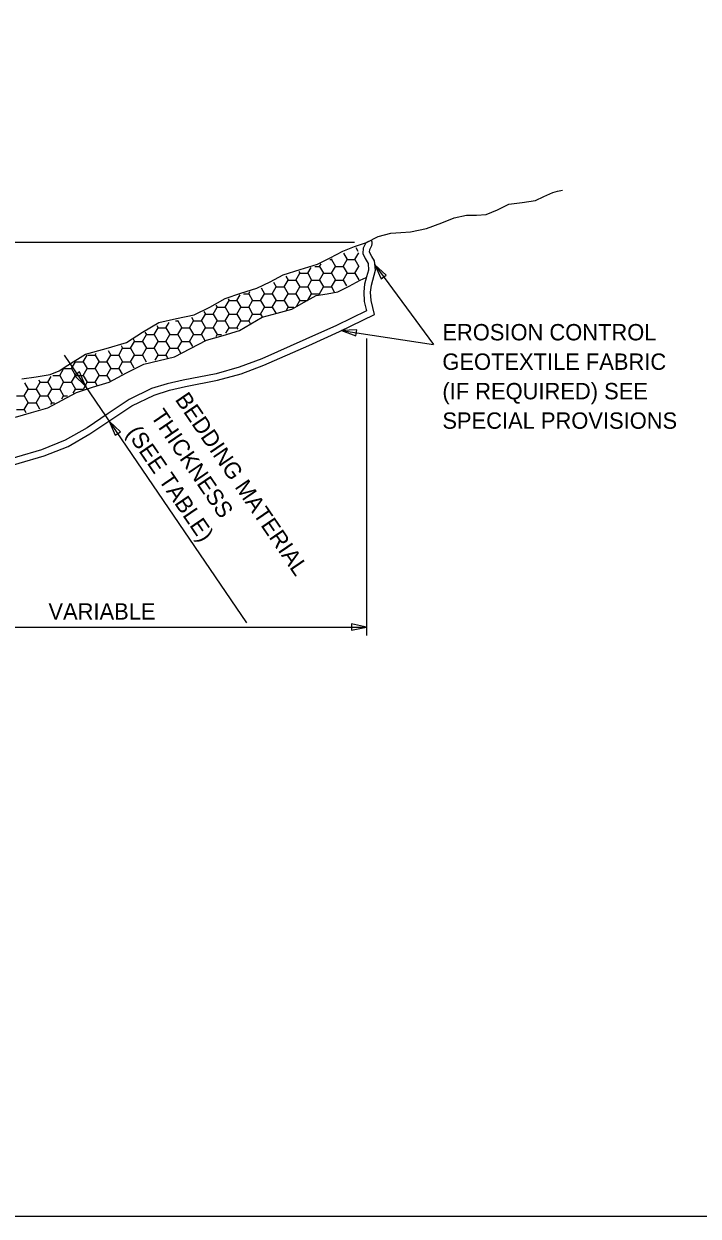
# Model space of a CAD drawing. Extents: x -439.1 to -407.9, y -458.1 to -436.2.
# Drawn here: x -424.66 to -418.48, y -458.05 to -447.12 of the extents above; entities that cross this region are included whole.
import ezdxf

# ---------------------------------------------------------------- set-up
doc = ezdxf.new("R2010")
doc.units = 0
doc.layers.add('Default', color=7, linetype='Continuous')
doc.layers.add('Draft_Named_Boundary', color=7, linetype='Continuous')

msp = doc.modelspace()

# ---------------------------------------------------------------- linework, layer by layer
at = {"layer": 'Default'}
for p, q in [((-421.625, -449.128), (-427.35, -449.128)), ((-421.613, -449.174), (-421.595, -449.206)), ((-421.523, -449.13), (-421.515, -449.128)), ((-421.472, -449.106), (-421.515, -449.128)), ((-421.851, -449.284), (-421.838, -449.284)), ((-421.838, -449.284), (-421.833, -449.276)), ((-421.838, -449.284), (-421.802, -449.347)), ((-421.73, -449.347), (-421.694, -449.284)), ((-421.727, -449.227), (-421.694, -449.284)), ((-421.694, -449.284), (-421.622, -449.284)), ((-421.622, -449.284), (-421.587, -449.224)), ((-421.622, -449.284), (-421.586, -449.347)), ((-422.163, -449.472), (-422.127, -449.409)), ((-422.135, -449.395), (-422.127, -449.409)), ((-422.127, -449.409), (-422.055, -449.409)), ((-422.055, -449.409), (-422.025, -449.358)), ((-422.055, -449.409), (-422.019, -449.472)), ((-421.991, -449.347), (-421.946, -449.347)), ((-421.946, -449.347), (-421.932, -449.322)), ((-421.946, -449.347), (-421.91, -449.409)), ((-421.946, -449.472), (-421.91, -449.409)), ((-421.91, -449.409), (-421.838, -449.409)), ((-421.838, -449.409), (-421.802, -449.347)), ((-421.838, -449.409), (-421.802, -449.472)), ((-421.802, -449.347), (-421.73, -449.347)), ((-421.73, -449.347), (-421.694, -449.409)), ((-421.73, -449.472), (-421.694, -449.409)), ((-421.694, -449.409), (-421.622, -449.409)), ((-421.622, -449.409), (-421.586, -449.347)), ((-421.622, -449.409), (-421.587, -449.47)), ((-421.44, -449.332), (-420.903, -450.062)), ((-422.369, -449.491), (-422.343, -449.534)), ((-422.271, -449.534), (-422.235, -449.472)), ((-422.255, -449.437), (-422.235, -449.472)), ((-422.235, -449.472), (-422.163, -449.472)), ((-422.163, -449.472), (-422.127, -449.534)), ((-422.055, -449.534), (-422.019, -449.472)), ((-422.019, -449.472), (-421.946, -449.472)), ((-421.946, -449.472), (-421.91, -449.534)), ((-421.838, -449.534), (-421.802, -449.472)), ((-421.802, -449.472), (-421.73, -449.472)), ((-421.73, -449.472), (-421.699, -449.526)), ((-422.704, -449.659), (-422.674, -449.607)), ((-422.643, -449.597), (-422.596, -449.597)), ((-422.596, -449.597), (-422.585, -449.577)), ((-422.596, -449.597), (-422.56, -449.659)), ((-422.488, -449.659), (-422.452, -449.597)), ((-422.483, -449.543), (-422.452, -449.597)), ((-422.452, -449.597), (-422.38, -449.597)), ((-422.38, -449.597), (-422.343, -449.534)), ((-422.38, -449.597), (-422.343, -449.659)), ((-422.343, -449.534), (-422.271, -449.534)), ((-422.271, -449.534), (-422.235, -449.597)), ((-422.271, -449.659), (-422.235, -449.597)), ((-422.235, -449.597), (-422.163, -449.597)), ((-422.163, -449.597), (-422.127, -449.534)), ((-422.163, -449.597), (-422.127, -449.659)), ((-422.127, -449.534), (-422.055, -449.534)), ((-422.055, -449.534), (-422.019, -449.597)), ((-422.053, -449.657), (-422.019, -449.597)), ((-422.019, -449.597), (-421.946, -449.597)), ((-421.946, -449.597), (-421.91, -449.534)), ((-421.946, -449.597), (-421.944, -449.602)), ((-421.91, -449.534), (-421.838, -449.534)), ((-421.838, -449.534), (-421.812, -449.579)), ((-422.921, -449.784), (-422.885, -449.722)), ((-422.896, -449.703), (-422.885, -449.722)), ((-422.885, -449.722), (-422.813, -449.722)), ((-422.813, -449.722), (-422.776, -449.659)), ((-422.813, -449.722), (-422.776, -449.784)), ((-422.785, -449.645), (-422.776, -449.659)), ((-422.776, -449.659), (-422.704, -449.659)), ((-422.704, -449.659), (-422.668, -449.722)), ((-422.704, -449.784), (-422.668, -449.722)), ((-422.668, -449.722), (-422.596, -449.722)), ((-422.596, -449.722), (-422.56, -449.659)), ((-422.596, -449.722), (-422.56, -449.784)), ((-422.56, -449.659), (-422.488, -449.659)), ((-422.488, -449.659), (-422.452, -449.722)), ((-422.488, -449.784), (-422.452, -449.722)), ((-422.452, -449.722), (-422.38, -449.722)), ((-422.38, -449.722), (-422.343, -449.659)), ((-422.38, -449.722), (-422.348, -449.776)), ((-422.343, -449.659), (-422.271, -449.659)), ((-422.271, -449.659), (-422.235, -449.722)), ((-422.25, -449.748), (-422.235, -449.722)), ((-422.235, -449.722), (-422.182, -449.722)), ((-422.155, -449.708), (-422.127, -449.659)), ((-422.127, -449.659), (-422.058, -449.659)), ((-423.268, -449.847), (-423.246, -449.847)), ((-423.246, -449.847), (-423.242, -449.841)), ((-423.246, -449.847), (-423.209, -449.909)), ((-423.137, -449.909), (-423.101, -449.847)), ((-423.121, -449.812), (-423.101, -449.847)), ((-423.101, -449.847), (-423.029, -449.847)), ((-423.029, -449.847), (-422.993, -449.784)), ((-423.029, -449.847), (-422.993, -449.909)), ((-423.007, -449.761), (-422.993, -449.784)), ((-422.993, -449.784), (-422.921, -449.784)), ((-422.921, -449.784), (-422.885, -449.847)), ((-422.921, -449.909), (-422.885, -449.847)), ((-422.885, -449.847), (-422.813, -449.847)), ((-422.813, -449.847), (-422.776, -449.784)), ((-422.813, -449.847), (-422.776, -449.909)), ((-422.776, -449.784), (-422.704, -449.784)), ((-422.704, -449.784), (-422.668, -449.847)), ((-422.704, -449.909), (-422.668, -449.847)), ((-422.668, -449.847), (-422.596, -449.847)), ((-422.596, -449.847), (-422.56, -449.784)), ((-422.596, -449.847), (-422.583, -449.87)), ((-422.56, -449.784), (-422.488, -449.784)), ((-422.488, -449.784), (-422.47, -449.815)), ((-423.547, -449.95), (-423.534, -449.972)), ((-423.462, -449.972), (-423.426, -449.909)), ((-423.438, -449.888), (-423.426, -449.909)), ((-423.426, -449.909), (-423.354, -449.909)), ((-423.354, -449.909), (-423.325, -449.86)), ((-423.354, -449.909), (-423.318, -449.972)), ((-423.246, -449.972), (-423.209, -449.909)), ((-423.209, -449.909), (-423.137, -449.909)), ((-423.137, -449.909), (-423.101, -449.972)), ((-423.029, -449.972), (-422.993, -449.909)), ((-422.993, -449.909), (-422.921, -449.909)), ((-422.921, -449.909), (-422.885, -449.972)), ((-422.805, -449.958), (-422.776, -449.909)), ((-422.776, -449.909), (-422.704, -449.909)), ((-422.704, -449.909), (-422.697, -449.922)), ((-421.747, -449.934), (-420.903, -450.062)), ((-423.765, -450.072), (-423.751, -450.097)), ((-423.679, -450.097), (-423.642, -450.034)), ((-423.656, -450.011), (-423.642, -450.034)), ((-423.642, -450.034), (-423.57, -450.034)), ((-423.57, -450.034), (-423.534, -449.972)), ((-423.57, -450.034), (-423.534, -450.097)), ((-423.534, -449.972), (-423.462, -449.972)), ((-423.462, -449.972), (-423.426, -450.034)), ((-423.462, -450.097), (-423.426, -450.034)), ((-423.426, -450.034), (-423.354, -450.034)), ((-423.354, -450.034), (-423.318, -449.972)), ((-423.354, -450.034), (-423.318, -450.097)), ((-423.318, -449.972), (-423.246, -449.972)), ((-423.246, -449.972), (-423.209, -450.034)), ((-423.246, -450.097), (-423.209, -450.034)), ((-423.209, -450.034), (-423.137, -450.034)), ((-423.137, -450.034), (-423.101, -449.972)), ((-423.137, -450.034), (-423.11, -450.082)), ((-423.101, -449.972), (-423.029, -449.972)), ((-423.029, -449.972), (-422.997, -450.027)), ((-422.894, -449.988), (-422.885, -449.972)), ((-422.885, -449.972), (-422.846, -449.972)), ((-421.515, -450.009), (-421.515, -452.73)), ((-424.286, -450.159), (-422.615, -452.612)), ((-424.112, -450.222), (-424.076, -450.161)), ((-424.07, -450.159), (-424.003, -450.159)), ((-424.003, -450.159), (-423.993, -450.142)), ((-424.003, -450.159), (-423.967, -450.222)), ((-423.895, -450.222), (-423.859, -450.159)), ((-423.883, -450.118), (-423.859, -450.159)), ((-423.859, -450.159), (-423.787, -450.159)), ((-423.787, -450.159), (-423.751, -450.097)), ((-423.787, -450.159), (-423.751, -450.222)), ((-423.751, -450.097), (-423.679, -450.097)), ((-423.679, -450.097), (-423.642, -450.159)), ((-423.679, -450.222), (-423.642, -450.159)), ((-423.642, -450.159), (-423.57, -450.159)), ((-423.57, -450.159), (-423.534, -450.097)), ((-423.57, -450.159), (-423.536, -450.22)), ((-423.534, -450.097), (-423.462, -450.097)), ((-423.462, -450.097), (-423.426, -450.159)), ((-423.452, -450.205), (-423.426, -450.159)), ((-423.426, -450.159), (-423.354, -450.159)), ((-423.354, -450.159), (-423.318, -450.097)), ((-423.354, -450.159), (-423.339, -450.185)), ((-423.318, -450.097), (-423.246, -450.097)), ((-423.246, -450.097), (-423.222, -450.138)), ((-424.328, -450.347), (-424.292, -450.285)), ((-424.292, -450.284), (-424.22, -450.284)), ((-424.22, -450.284), (-424.184, -450.222)), ((-424.22, -450.284), (-424.184, -450.347)), ((-424.186, -450.218), (-424.184, -450.222)), ((-424.184, -450.222), (-424.112, -450.222)), ((-424.112, -450.222), (-424.075, -450.284)), ((-424.112, -450.347), (-424.075, -450.284)), ((-424.075, -450.284), (-424.003, -450.284)), ((-424.003, -450.284), (-423.967, -450.222)), ((-424.003, -450.284), (-423.967, -450.347)), ((-423.967, -450.222), (-423.895, -450.222)), ((-423.895, -450.222), (-423.859, -450.284)), ((-423.895, -450.347), (-423.859, -450.284)), ((-423.859, -450.284), (-423.787, -450.284)), ((-423.787, -450.284), (-423.751, -450.222)), ((-423.787, -450.284), (-423.757, -450.336)), ((-423.751, -450.222), (-423.679, -450.222)), ((-423.679, -450.222), (-423.648, -450.275)), ((-424.521, -450.388), (-424.508, -450.409)), ((-424.436, -450.409), (-424.406, -450.357)), ((-424.391, -450.347), (-424.328, -450.347)), ((-424.328, -450.347), (-424.292, -450.409)), ((-424.22, -450.409), (-424.184, -450.347)), ((-424.184, -450.347), (-424.112, -450.347)), ((-424.112, -450.347), (-424.075, -450.409)), ((-424.003, -450.409), (-423.967, -450.347)), ((-423.967, -450.347), (-423.895, -450.347)), ((-423.895, -450.347), (-423.866, -450.397)), ((-424.653, -450.534), (-424.617, -450.472)), ((-424.651, -450.413), (-424.617, -450.472)), ((-424.617, -450.472), (-424.545, -450.472)), ((-424.545, -450.472), (-424.508, -450.409)), ((-424.545, -450.472), (-424.508, -450.534)), ((-424.508, -450.409), (-424.436, -450.409)), ((-424.436, -450.409), (-424.4, -450.472)), ((-424.436, -450.534), (-424.4, -450.472)), ((-424.4, -450.472), (-424.328, -450.472)), ((-424.328, -450.472), (-424.292, -450.409)), ((-424.328, -450.472), (-424.292, -450.534)), ((-424.292, -450.409), (-424.22, -450.409)), ((-424.22, -450.409), (-424.184, -450.472)), ((-424.205, -450.508), (-424.184, -450.472)), ((-424.184, -450.472), (-424.112, -450.472)), ((-424.111, -450.472), (-424.075, -450.409)), ((-424.085, -450.44), (-424.091, -450.445)), ((-424.075, -450.409), (-424.003, -450.409)), ((-424.003, -450.409), (-423.988, -450.436)), ((-424.725, -450.534), (-424.653, -450.534)), ((-424.653, -450.534), (-424.617, -450.597)), ((-424.653, -450.659), (-424.617, -450.597)), ((-424.617, -450.597), (-424.545, -450.597)), ((-424.545, -450.597), (-424.508, -450.534)), ((-424.545, -450.597), (-424.512, -450.653)), ((-424.508, -450.534), (-424.436, -450.534)), ((-424.436, -450.534), (-424.4, -450.597)), ((-424.41, -450.614), (-424.4, -450.597)), ((-424.4, -450.597), (-424.377, -450.597)), ((-424.307, -450.561), (-424.292, -450.534)), ((-424.292, -450.534), (-424.255, -450.534)), ((-424.725, -450.659), (-424.653, -450.659)), ((-424.653, -450.659), (-424.638, -450.685)), ((-423.868, -450.759), (-423.874, -450.764)), ((-426.203, -452.652), (-421.515, -452.652))]:
    msp.add_line(p, q, dxfattribs=at)
for points in [[(-421.515, -449.128), (-421.408, -449.074), (-421.292, -449.042), (-421.202, -449.035), (-421.112, -449.031), (-420.967, -449.001), (-420.826, -448.948), (-420.714, -448.903), (-420.6, -448.877), (-420.509, -448.877), (-420.421, -448.871), (-420.317, -448.827), (-420.213, -448.778), (-420.09, -448.76), (-419.969, -448.743), (-419.89, -448.707), (-419.81, -448.669), (-419.766, -448.656), (-419.72, -448.647)], [(-424.675, -450.378), (-424.545, -450.36), (-424.416, -450.339), (-424.332, -450.303), (-424.253, -450.252), (-424.093, -450.152), (-423.903, -450.098), (-423.715, -450.043), (-423.568, -449.949), (-423.419, -449.86), (-423.258, -449.824), (-423.095, -449.791), (-422.953, -449.719), (-422.813, -449.641), (-422.667, -449.593), (-422.52, -449.547), (-422.4, -449.487), (-422.28, -449.425), (-422.123, -449.375), (-421.966, -449.326), (-421.849, -449.267), (-421.733, -449.206), (-421.626, -449.163), (-421.515, -449.128)], [(-421.523, -449.13), (-421.547, -449.181), (-421.551, -449.229), (-421.529, -449.274), (-421.502, -449.319), (-421.497, -449.38), (-421.515, -449.441)], [(-421.472, -449.519), (-421.435, -449.381), (-421.443, -449.297), (-421.469, -449.256), (-421.49, -449.216), (-421.486, -449.193), (-421.485, -449.191)], [(-421.485, -449.191), (-421.468, -449.156), (-421.464, -449.141), (-421.466, -449.124), (-421.472, -449.106)], [(-424.732, -450.728), (-424.585, -450.685), (-424.437, -450.642), (-424.306, -450.573), (-424.175, -450.502), (-424.026, -450.454), (-423.876, -450.407), (-423.717, -450.322), (-423.556, -450.243), (-423.415, -450.21), (-423.276, -450.176), (-423.129, -450.1), (-422.983, -450.023), (-422.83, -449.981), (-422.681, -449.935), (-422.577, -449.872), (-422.472, -449.812), (-422.336, -449.776), (-422.2, -449.739), (-422.089, -449.674), (-421.977, -449.615), (-421.878, -449.597), (-421.779, -449.579), (-421.675, -449.529), (-421.573, -449.472), (-421.547, -449.46), (-421.52, -449.45)], [(-421.515, -449.441), (-421.534, -449.51), (-421.542, -449.581), (-421.537, -449.668), (-421.515, -449.753)], [(-421.443, -449.787), (-421.475, -449.659), (-421.48, -449.583), (-421.472, -449.519)], [(-421.515, -449.753), (-421.792, -449.887), (-422.072, -450.015), (-422.476, -450.193), (-422.682, -450.27), (-422.895, -450.33), (-423.195, -450.389), (-423.343, -450.422), (-423.486, -450.467), (-423.69, -450.568), (-423.884, -450.694), (-424.077, -450.825), (-424.277, -450.94), (-424.496, -451.027), (-424.724, -451.095), (-424.952, -451.161), (-425.173, -451.244), (-425.43, -451.382), (-425.689, -451.518), (-425.941, -451.599), (-426.203, -451.647)], [(-426.195, -451.709), (-425.924, -451.66), (-425.664, -451.575), (-425.405, -451.44), (-425.147, -451.301), (-424.926, -451.218), (-424.698, -451.151), (-424.47, -451.084), (-424.25, -450.997), (-424.051, -450.882), (-423.859, -450.752), (-423.666, -450.626), (-423.463, -450.526), (-423.322, -450.481), (-423.176, -450.449), (-422.881, -450.391), (-422.665, -450.33), (-422.456, -450.252), (-422.046, -450.071), (-421.765, -449.943), (-421.443, -449.787)]]:
    msp.add_lwpolyline(points, dxfattribs=at)
for points in [[(-421.335, -449.427), (-421.44, -449.332), (-421.381, -449.461)], [(-421.335, -449.427), (-421.44, -449.332), (-421.381, -449.461)], [(-421.606, -449.927), (-421.747, -449.934), (-421.615, -449.983)], [(-421.606, -449.927), (-421.747, -449.934), (-421.615, -449.983)], [(-424.193, -450.346), (-424.091, -450.445), (-424.145, -450.314)], [(-424.193, -450.346), (-424.091, -450.445), (-424.145, -450.314)], [(-423.772, -450.862), (-423.874, -450.764), (-423.82, -450.894)], [(-423.772, -450.862), (-423.874, -450.764), (-423.82, -450.894)], [(-421.654, -452.681), (-421.515, -452.652), (-421.654, -452.623)]]:
    msp.add_lwpolyline(points, close=True, dxfattribs=at)
at = {"layer": 'Draft_Named_Boundary'}
msp.add_lwpolyline([(-439.109, -458.051), (-407.859, -458.051), (-407.859, -437.676), (-439.109, -437.676)], close=True, dxfattribs=at)

# ---------------------------------------------------------------- texts
at = {"layer": 'Default'}
for s, p in [('EROSION CONTROL ', (-420.821, -450.025)), ('GEOTEXTILE FABRIC ', (-420.821, -450.295)), ('(IF REQUIRED) SEE ', (-420.821, -450.565)), ('SPECIAL PROVISIONS', (-420.821, -450.835)), ('VARIABLE', (-424.431, -452.584))]:
    msp.add_text(s, height=0.15, dxfattribs=at).set_placement(p)
for s, p in [('BEDDING MATERIAL ', (-423.276, -450.567)), ('THICKNESS ', (-423.499, -450.72)), ('(SEE TABLE)', (-423.722, -450.872))]:
    msp.add_text(s, height=0.15, rotation=304.3, dxfattribs=at).set_placement(p)

doc.saveas('drawing.dxf')
